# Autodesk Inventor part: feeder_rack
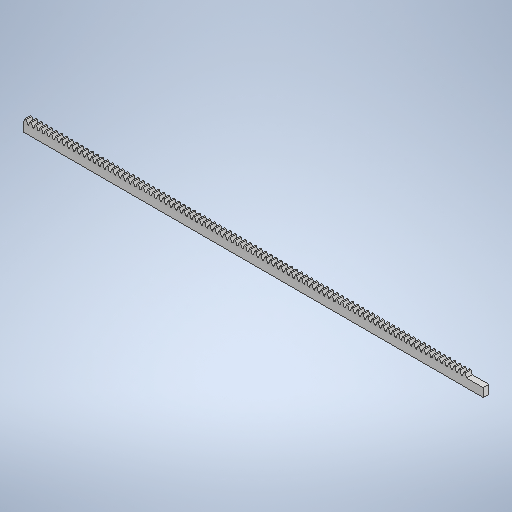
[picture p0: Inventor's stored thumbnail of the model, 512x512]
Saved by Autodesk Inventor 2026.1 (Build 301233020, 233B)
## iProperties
Company: meta-matic.com
Created: 2026-11
Part Number: feeder_rack
Material: Generic
Description: Rack Gear - meta-matic-generator 1.3
Document SubType Name: Modeling
Designer: alolo
Authority: META-MATIC-ID: 3dc0ee3cef1d
Density: 1 g/cm^3
Appearance: Default
Sending System: Open CASCADE
Preprocessor: meta-matic-generator 1.3
Title: Rack Gear_3dc0ee3cef1d
Author: Takahashi Mizuki @tkhsmz
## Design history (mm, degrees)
feature "Base1"
sketch "Sketch1"
  geometry: L1 (10, 10.5)-(0, 10.5) reference; L2 (0, 10.5)-(10, 10.5); L3 (10, 10.5)-(10, 0); L4 (10, 0)-(0, 0); L5 (0, 0)-(0, 10.5); 1 further point
  constraints: 8 end point, 2 parallel, 1 horizontal, 1 perpendicular
extrude "Extrusion1" join sketch "Sketch1" distance "d0" = 40; taper "d1" = 0 deg
sketch "Sketch2"
  geometry: L1 (0, 0)-(0, 10.5) reference; L2 (0, 0)-(586.637, 0) reference; L3 (586.637, 10.5)-(586.637, 0) reference; L4 (545.976, 10.5)-(586.637, 10.5) reference; L5 (544.338, 15)-(545.976, 10.5) reference; L6 (542.653, 15)-(544.338, 15) reference; L7 (541.015, 10.5)-(542.653, 15) reference; L8 (539.693, 10.5)-(541.015, 10.5) reference; L9 (538.055, 15)-(539.693, 10.5) reference; L10 (536.369, 15)-(538.055, 15) reference; L11 (534.732, 10.5)-(536.369, 15) reference; L12 (533.41, 10.5)-(534.732, 10.5) reference; L13 (531.772, 15)-(533.41, 10.5) reference; L14 (530.086, 15)-(531.772, 15) reference; L15 (528.448, 10.5)-(530.086, 15) reference; L16 (527.127, 10.5)-(528.448, 10.5) reference; L17 (525.489, 15)-(527.127, 10.5) reference; L18 (523.803, 15)-(525.489, 15) reference; L19 (522.165, 10.5)-(523.803, 15) reference; L20 (520.844, 10.5)-(522.165, 10.5) reference; L21 (519.206, 15)-(520.844, 10.5) reference; L22 (517.52, 15)-(519.206, 15) reference; L23 (515.882, 10.5)-(517.52, 15) reference; L24 (514.56, 10.5)-(515.882, 10.5) reference; L25 (512.922, 15)-(514.56, 10.5) reference; L26 (511.237, 15)-(512.922, 15) reference; L27 (509.599, 10.5)-(511.237, 15) reference; L28 (508.277, 10.5)-(509.599, 10.5) reference; L29 (506.639, 15)-(508.277, 10.5) reference; L30 (504.954, 15)-(506.639, 15) reference; L31 (503.316, 10.5)-(504.954, 15) reference; L32 (501.994, 10.5)-(503.316, 10.5) reference; L33 (500.356, 15)-(501.994, 10.5) reference; L34 (498.67, 15)-(500.356, 15) reference; L35 (497.033, 10.5)-(498.67, 15) reference; L36 (495.711, 10.5)-(497.033, 10.5) reference; L37 (494.073, 15)-(495.711, 10.5) reference; L38 (492.387, 15)-(494.073, 15) reference; L39 (490.749, 10.5)-(492.387, 15) reference; L40 (489.428, 10.5)-(490.749, 10.5) reference; L41 (487.79, 15)-(489.428, 10.5) reference; L42 (486.104, 15)-(487.79, 15) reference; L43 (484.466, 10.5)-(486.104, 15) reference; L44 (483.144, 10.5)-(484.466, 10.5) reference; L45 (481.507, 15)-(483.144, 10.5) reference; L46 (479.821, 15)-(481.507, 15) reference; L47 (478.183, 10.5)-(479.821, 15) reference; L48 (476.861, 10.5)-(478.183, 10.5) reference; L49 (475.223, 15)-(476.861, 10.5) reference; L50 (473.538, 15)-(475.223, 15) reference; L51 (471.9, 10.5)-(473.538, 15) reference; L52 (470.578, 10.5)-(471.9, 10.5) reference; L53 (468.94, 15)-(470.578, 10.5) reference; L54 (467.254, 15)-(468.94, 15) reference; L55 (465.617, 10.5)-(467.254, 15) reference; L56 (464.295, 10.5)-(465.617, 10.5) reference; L57 (462.657, 15)-(464.295, 10.5) reference; L58 (460.971, 15)-(462.657, 15) reference; L59 (459.333, 10.5)-(460.971, 15) reference; L60 (458.012, 10.5)-(459.333, 10.5) reference; L61 (456.374, 15)-(458.012, 10.5) reference; L62 (454.688, 15)-(456.374, 15) reference; L63 (453.05, 10.5)-(454.688, 15) reference; L64 (451.728, 10.5)-(453.05, 10.5) reference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; 1 further point
extrude "Extrusion2" cut sketch "Sketch2" distance "d2" = 3; taper "d3" = 0 deg
sketch "Sketch3"
  geometry: L1 (3, 10.5)-(3, 0) reference; L2 (3, 0)-(10, 0) reference; L3 (10, 0)-(10, 10.5) reference; L4 (10, 10.5)-(3, 10.5) reference; 1 further point
extrude "Extrusion3" cut sketch "Sketch3" distance "d4" = 20; taper "d5" = 0 deg
body "Solid1"
node "Projected Loop1"
node "Projected Loop2"
